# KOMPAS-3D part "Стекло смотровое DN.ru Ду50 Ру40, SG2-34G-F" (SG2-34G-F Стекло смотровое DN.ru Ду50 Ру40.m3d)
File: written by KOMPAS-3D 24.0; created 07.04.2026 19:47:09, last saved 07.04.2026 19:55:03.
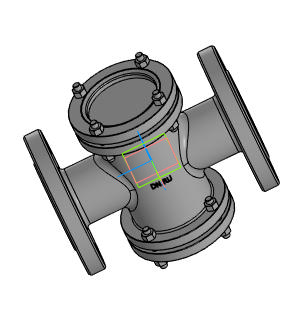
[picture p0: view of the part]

Document properties: Автор: Main; Полное имя файла: SG2-34G-FСтекло смотровое DN.ru Ду50 Ру40 (3d).cdw

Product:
- Body: Тело 1  | qty 1
    Масса: 11.518228
- Part/product: Стекло смотровое DN.ru Ду50 Ру40  | designation SG2-34G-F
    Масса: 10.5
    Раздел спецификации: Прочие изделия
    Форматы листов документа: A4
    Примечание: D500-00084

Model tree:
1. Операция без истории:1

Expressions: SG2-34G-F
